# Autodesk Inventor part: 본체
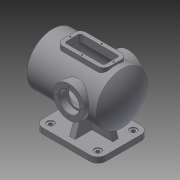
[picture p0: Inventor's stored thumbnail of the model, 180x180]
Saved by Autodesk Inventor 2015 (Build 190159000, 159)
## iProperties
Created: 2021-11
Part Number: 본체
Material: 일반
Document SubType Name: Modeling
Designer: 1019876
Density: 1 g/cm^3
Appearance: 기본값
Author: 1019876
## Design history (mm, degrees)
sketch "스케치1"
  geometry: L1 (80, -65)-(-80, -65); L2 (-80, -65)-(-80, 65); L3 (-80, 65)-(80, 65); L4 (80, 65)-(80, -65); L5 (80, -65)-(-80, 65); L6 (-80, -65)-(80, 65); 1 further point
  constraints: 12 end point, 2 midpoint, 2 parallel, 1 horizontal, 1 perpendicular
  dimensions: "d0" = 130 distance of L3.end L1.start; "d1" = 160 distance of L2.end L3.end
extrude "돌출1" new body sketch "스케치1" distance "d2" = 14; taper "d3" = 0 deg
fillet "모깎기1" dims "d4" = 20
sketch "스케치2"
  geometry: A1 r 20 centre (-60, 45) between (-60, 65) and (-80, 45) reference; A2 r 20 centre (-60, -45) between (-80, -45) and (-60, -65) reference; A3 r 20 centre (60, -45) between (60, -65) and (80, -45) reference; A4 r 20 centre (60, 45) between (80, 45) and (60, 65) reference; 1 further point
hole "구멍1" sketch "스케치2" at (-60, -45), (60, -45), (60, 45), (-60, 45) diameter "d5" = 9; stored, may be unused: countersink angle "d9" = 90 deg, drill point angle "d11" = 118 deg; dims "d6" = 6, "d7" = 18, "d8" = 2, "d10" = 8
sketch "스케치3"
  geometry: L1 (60, -7)-(-60, -7); L2 (-60, -7)-(-60, 7); L3 (-60, 7)-(60, 7); L4 (60, 7)-(60, -7); L5 (60, -7)-(-60, 7); L6 (-60, -7)-(60, 7); L7 (7, -50)-(-7, -50); L8 (-7, -50)-(-7, 50); L9 (-7, 50)-(7, 50); L10 (7, 50)-(7, -50); L11 (7, -50)-(-7, 50); L12 (-7, -50)-(7, 50); 1 further point
  constraints: 24 end point, 4 midpoint, 4 parallel, 2 horizontal, 2 perpendicular
  dimensions: "d12" = 14 distance of L8.end L9.end; "d13" = 14 distance of L1.end L2.end; "d14" = 120 distance of L1.start L1.end; "d15" = 100 distance of L9.end L7.start
extrude "돌출2" join sketch "스케치3" distance "d16" = 100; taper "d17" = 0 deg
feature "면 기울기1" dims angle "d18" = 20 deg
feature "면 기울기2" dims angle "d19" = 20 deg
sketch "스케치6"
  geometry: L1 (100, 114)-(-100, 114); L2 (-75.993, 179)-(100, 179); L3 (100, 179)-(100, 114); L4 (-100, 114)-(100, 179); L5 (80, 14)-(80, 0) reference; L6 (80, 0)-(-80, 0) reference; L7 (-80, 0)-(-80, 14) reference; L8 (-80, 14)-(-60, 14) reference; L9 (-60, 14)-(-23.603, 114) reference; L10 (-23.603, 114)-(23.603, 114) reference; L11 (23.603, 114)-(60, 14) reference; L12 (60, 14)-(80, 14) reference; A1 r 100 centre (0, 114) between (-75.993, 179) and (-100, 114); 5 further points
  constraints: 8 end point, 2 horizontal alignment, 2 midpoint, 2 point on circle, 2 vertical alignment, 1 centre point, 1 horizontal, 1 parallel, 1 point on line
  dimensions: "d28" = 114 distance from line of point (0, 0) L1; "d31" = 65 distance of L2.end L1.start; "d33" = 20 distance between parallel lines of L5 L3; "d35" = 100 radius of A1
revolve "회전1" sketch "스케치6" stored, may be unused: angle "d36" = 90 deg
sketch "스케치8"
  geometry: L1 (80, 14)-(80, 0) reference; L2 (80, 0)-(-80, 0) reference; L3 (-80, 0)-(-80, 14) reference; L4 (-80, 14)-(-60, 14) reference; L5 (-60, 14)-(-47.261, 49) reference; L6 (-47.261, 49)-(-75.993, 49) reference; L7 (-75.993, 179)-(100, 179) reference; L8 (100, 179)-(100, 49) reference; L9 (100, 49)-(47.261, 49) reference; L10 (47.261, 49)-(60, 14) reference; L11 (60, 14)-(80, 14) reference; L12 (-71.239, 169)-(85, 169); L13 (85, 169)-(85, 114); L14 (85, 114)-(-90, 114); A1 r 100 centre (0, 114) between (-75.993, 179) and (-75.993, 49) reference; A2 r 90 centre (0, 114) between (-71.239, 169) and (-90, 114); 1 further point
  constraints: 6 end point, 2 point on circle, 1 centre point, 1 horizontal, 1 parallel, 1 perpendicular, 1 point on line
  dimensions: "d40" = 10 radial gap between concentric circles of A1 A2; "d41" = 55 distance of L12.end L13.end; "d42" = 15 distance between parallel lines of L13 L8
revolve "회전2" sketch "스케치8" stored, may be unused: angle "d43" = 90 deg
sketch "스케치9"
  geometry: C1 r 65 at (0, 0) reference; C2 r 47.5 at (0, 0); 1 further point
  constraints: 1 centre point, 1 coincident
  dimensions: "d44" = 95 diameter of C2
extrude "돌출6" join sketch "스케치9" distance "d45" = 10; taper "d46" = 0 deg
sketch "스케치10"
  geometry: C1 r 47.5 at (0, 0) reference; C2 r 32.5 at (0, 0); 1 further point
  constraints: 1 centre point, 1 coincident
  dimensions: "d47" = 65 diameter of C2
extrude "돌출7" cut sketch "스케치10" distance "d48" = 25; taper "d49" = 0 deg
chamfer "모따기1" distance "d50" = 1; stored, may be unused: second distance "d51" = 2, angle "d52" = 45 deg
sketch "스케치12"
  geometry: C1 r 47.5 at (0, 0) reference; 2 further points
  constraints: 1 horizontal alignment
  dimensions: "d53" = 40 distance of C1.centre point (40, 0)
hole "구멍2" sketch "스케치12" at (40, 0) diameter "d54" = 3.242; stored, may be unused: countersink angle "d58" = 90 deg, drill point angle "d60" = 118 deg; dims "d55" = 11, "d56" = 4, "d57" = 2, "d59" = 13
node "작업 평면2"
sketch "스케치14"
  geometry: L1 (110, 66.5)-(110, 161.5) reference; C1 r 40 at (-17, 114); 1 further point
  constraints: 1 centre point
  dimensions: "d121" = 80 diameter of C1; "d123" = 127 distance from line of L1 C1.centre; "d124" = 114 vertical distance of point (0, 0) C1.centre
extrude "돌출8" join sketch "스케치14" stored distance "d68" = 25; taper "d69" = 0 deg
node "작업 평면3"
sketch "스케치17"
  geometry: L1 (-60, 30)-(60, 30); L2 (60, 30)-(60, -30); L3 (60, -30)-(-60, -30); L4 (-60, -30)-(-60, 30); L5 (-60, 30)-(60, -30); L6 (60, 30)-(-60, -30); L7 (110, -47.5)-(110, 47.5) reference; 2 further points
  constraints: 12 end point, 2 midpoint, 2 parallel, 1 horizontal, 1 perpendicular
  dimensions: "d93" = 120 distance of L2.end L3.end; "d94" = 50 distance between parallel lines of L7 L2; "d96" = 30 distance from line of L3 point (0, 0); "d97" = 30 distance from line of L1 point (0, 0)
extrude "돌출9" join sketch "스케치17" stored distance "d98" = 25; taper "d99" = 0 deg
sketch "스케치18"
  geometry: L1 (60, 30)-(-60, 30) reference; L2 (-60, 30)-(-60, -30) reference; L3 (-60, -30)-(60, -30) reference; L4 (60, -30)-(60, 30) reference; L5 (-50, 20)-(50, 20); L6 (50, 20)-(50, -20); L7 (50, -20)-(-50, -20); L8 (-50, -20)-(-50, 20); 1 further point
  constraints: 8 end point, 3 other
  dimensions: "d100" = 10 distance between parallel lines of L1 L5
extrude "돌출10" cut sketch "스케치18" distance "d101" = 60; taper "d102" = 0 deg
fillet "모깎기3" dims "d103" = 15
fillet "모깎기4" dims "d104" = 5
sketch "스케치19"
  geometry: 2 further points
  constraints: 1 vertical alignment
  dimensions: "d105" = 25 distance of point (0, 0) point (0, 25)
hole "구멍5" sketch "스케치19" at (0, 25) diameter "d106" = 3.242; stored, may be unused: countersink angle "d110" = 90 deg, drill point angle "d112" = 118 deg; dims "d107" = 9, "d108" = 52, "d109" = 18, "d111" = 11
sketch "스케치20"
  geometry: 2 further points
  constraints: 1 horizontal alignment
  dimensions: "d113" = 55 distance of point (0, 0) point (-55, 0)
hole "구멍6" sketch "스케치20" at (-55, 0) diameter "d114" = 3.242; stored, may be unused: countersink angle "d118" = 90 deg, drill point angle "d120" = 118 deg; dims "d115" = 9, "d116" = 52, "d117" = 18, "d119" = 11
sketch "스케치23"
  geometry: C1 r 40 at (0, 0) reference; 1 further point
hole "구멍7" sketch "스케치23" at (0, 0) diameter "d125" = 42; stored, may be unused: countersink angle "d129" = 90 deg, drill point angle "d131" = 0 deg; dims "d126" = 9, "d127" = 52, "d128" = 18, "d130" = 75
sketch "스케치24"
  geometry: C1 r 26 at (0, 0) reference; 2 further points
  constraints: 1 horizontal alignment
  dimensions: "d132" = 32.5 distance of C1.centre point (32.5, 0)
hole "구멍8" sketch "스케치24" at (32.5, 0) diameter "d133" = 3.242; stored, may be unused: countersink angle "d137" = 90 deg, drill point angle "d139" = 118 deg; dims "d134" = 11, "d135" = 52, "d136" = 18, "d138" = 13
chamfer "모따기3" distance "d143" = 1; stored, may be unused: second distance "d144" = 2, angle "d145" = 45 deg
fillet "모깎기5" dims "d146" = 0.3
node "솔리드1"
pattern_circular "원형 패턴1" dims angle "d62" = 360 deg
mirror "대칭2"
mirror "대칭3"
pattern_circular "원형 패턴3" dims angle "d141" = 360 deg
mirror "대칭4"
node "절단 모서리 투영1"
node "절단 모서리 투영2"
other parameters: "d65" = -75, "d92" = -184
